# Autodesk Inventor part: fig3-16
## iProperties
Created: 2005-02
Part Number: fig3-16
Document SubType Name: Modeling
Designer: CADCIM
Manufacturer: Standard
Standards Organization: Custom
Author: CADCIM
